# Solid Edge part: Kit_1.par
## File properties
Sűrűség: 0,000 kg/m^3
Pontosság: 0,990
Author: ahadarics
Last saved by: ahadarics
Revision: 76
Username: ahadarics
Dokumentum tartalom típus: 0
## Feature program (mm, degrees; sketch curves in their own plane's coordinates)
base feature "unnamed BaseFeature 1"
sketch for "Furat_1" plane through (0, -48.5, 12) normal (0, 0, 1) x-axis (0, 1, 0)
  hole centre (-0.25, 0) bore radius 4.283
hole "Furat_1" nominal diameter 9.728 finite  ThreadDepth = 7.5 mm
chamfer "Letörés_1" setback 0.7
thread "unnamed Thread 1"
chamfer "Letörés_2" setback 1.5
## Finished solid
Body 1: solid body, 49 faces, 54 edges, 8 vertices.
  Faces by surface: plane 15, cylinder 14, cone 13, torus 7
  Edges by curve: circle 46, intersection 4, line 4
Bounding box of the edges (mm; curved faces can reach further): 27.000 x 37.500 x 25.500, from (-13.5, -76.25, -13.5) to (13.5, -38.75, 12).
Cylindrical faces by radius (mm): R4.15 x1, R4.25 x1, R4.28 x1, R4.283 x1, R4.55 x1, R6 x1, R6.05 x1, R7.05 x1, R7.1 x1, R9.85 x1, R11 x2, R11.1 x1, R13.5 x1
Conical faces (half-angle, radius in mm at the cone's reference point): 0.1788 deg R5.7706 x1, 15 deg R7.05 x1, 19.7315 deg R4.0176 x1, 20.542 deg R4.55 x1, 21.5244 deg R5.2703 x1, 24.3997 deg R4.55 x1, 45 deg R4.983 x1, 45 deg R6.15 x1, 45 deg R6.2 x1, 45 deg R11 x1, 59 deg R2.1415 x2, 60 deg R10.425 x1
Toroidal faces (ring radius, tube radius in mm): R4.2 r0.2 x1, R4.3 r0.3 x1, R5.6424 r0.4 x1, R5.85 r0.2 x1, R6.85 r0.2 x1, R6.9 r0.2 x2
Planar faces by outward normal: +y 5, +z 2, -y 8
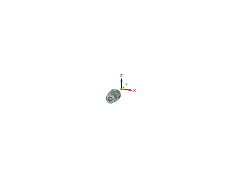
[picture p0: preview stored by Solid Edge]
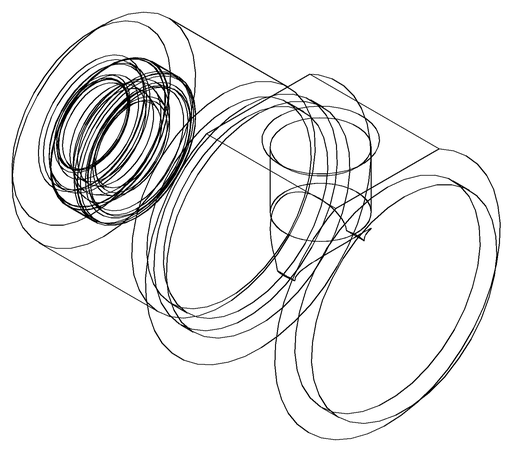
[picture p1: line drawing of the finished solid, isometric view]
